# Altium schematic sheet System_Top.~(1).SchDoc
size A3; SheetNumber: 1; SheetTotal: 6; PageSetup: Record=PageOptions¦CenterHorizontal=True¦CenterVertical=True¦PrintScale=1.01¦XCorrection=1.00¦YCorrection=1.00¦PrintKind=1¦BorderSize=5000000¦LeftOffset=0¦BottomOffset=0¦Orientation=2¦PaperLength=1000¦PaperWidth=1000¦Scale=100¦PaperSource=7¦PrintQuality=600¦MediaType=1¦DitherType=10¦PaperKind=A3¦PrintScaleMode=1
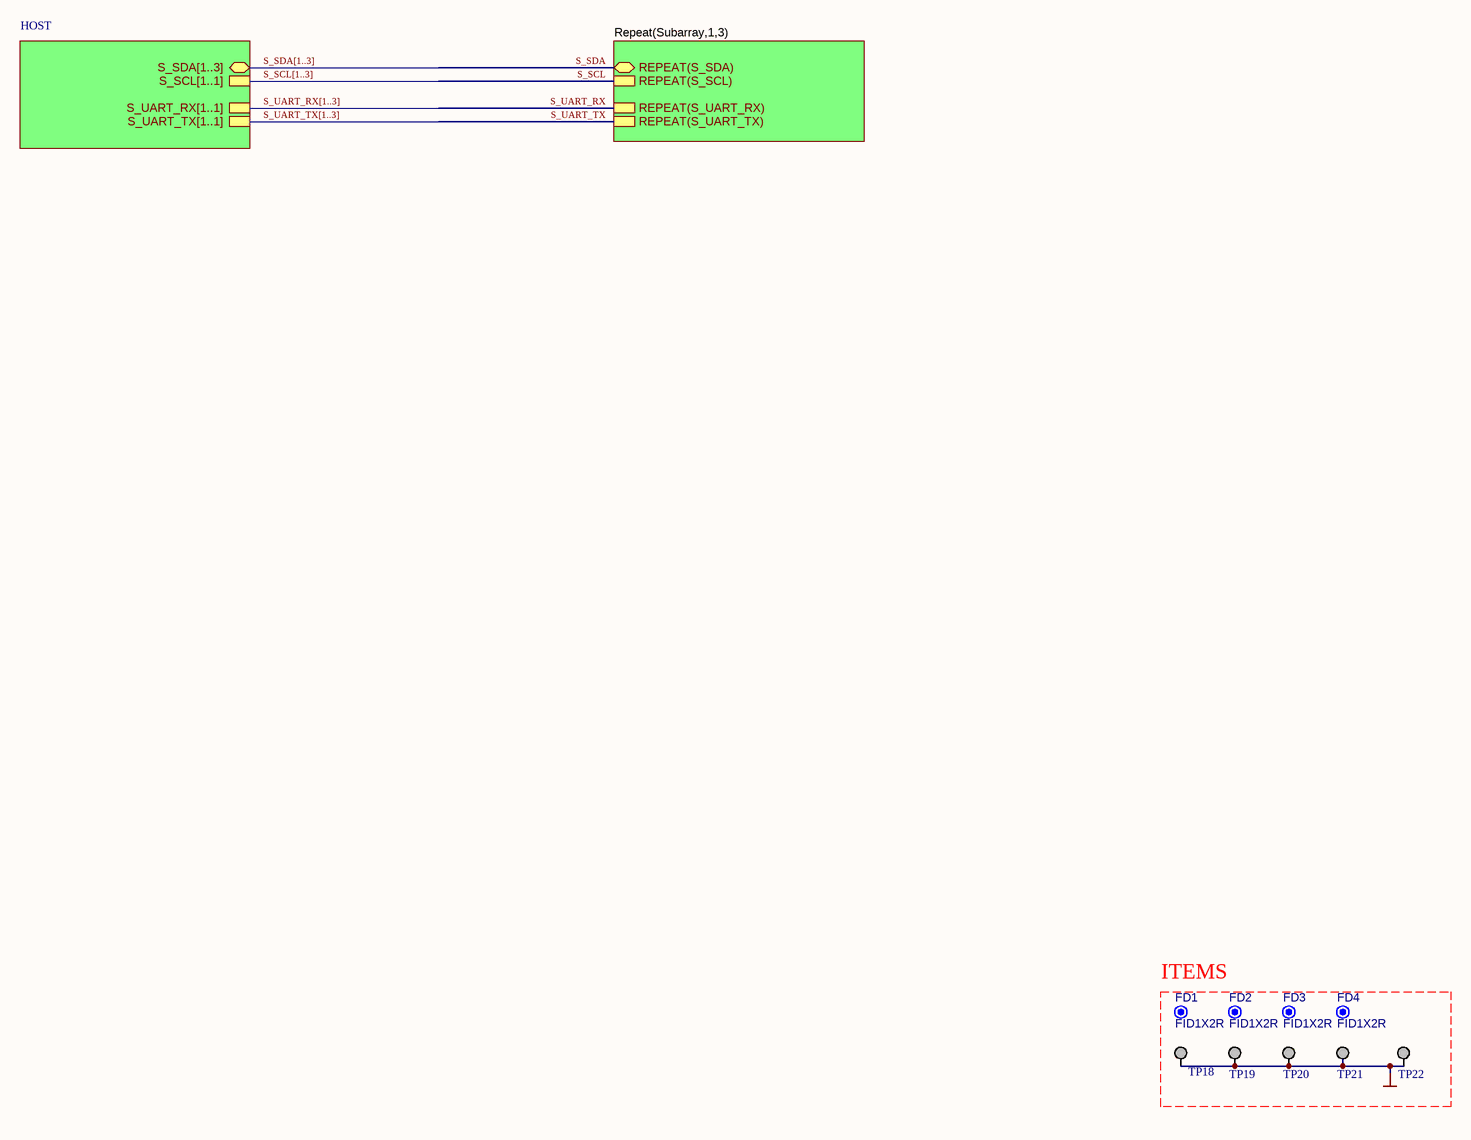
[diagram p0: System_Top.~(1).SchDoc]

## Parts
FD1  FID1X2R  [FID1X2R]  (no BOM)
FD2  FID1X2R  [FID1X2R]  (no BOM)
FD3  FID1X2R  [FID1X2R]  (no BOM)
FD4  FID1X2R  [FID1X2R]  (no BOM)
TP18  TP_DC_1MM WZ  [TP_DC_1mm]  (value not drawn)
TP19  TP_DC_1MM WZ  [TP_DC_1mm]  (value not drawn)
TP20  TP_DC_1MM WZ  [TP_DC_1mm]  (value not drawn)
TP21  TP_DC_1MM WZ  [TP_DC_1mm]  (value not drawn)
TP22  TP_DC_1MM WZ  [TP_DC_1mm]  (value not drawn)

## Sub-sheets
HOST = HOST.SchDoc: S_SCL[1..1], S_SDA[1..3] (bidir), S_UART_RX[1..1], S_UART_TX[1..1]
Repeat(Subarray,1,3) = Subarray.SchDoc: REPEAT(S_SCL), REPEAT(S_SDA) (bidir), REPEAT(S_UART_RX), REPEAT(S_UART_TX)

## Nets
GND: TP18.1 TP19.1 TP20.1 TP21.1 TP22.1

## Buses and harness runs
bus S_SCL[1..3] = sheet HOST/S_SCL[1..1]
bus S_SDA[1..3] = sheet HOST/S_SDA[1..3]
bus S_UART_RX[1..3] = sheet HOST/S_UART_RX[1..1]
bus S_UART_TX[1..3] = sheet HOST/S_UART_TX[1..1]

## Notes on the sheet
- ITEMS

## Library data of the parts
FD1-FD4 = CMP-00028-00005-4: Fiducial - Round 1x2mm; Barcode: 999999
TP18-TP22 = CMP-00030-3: DC, 1mm Test Point, SMT; Barcode: 999999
